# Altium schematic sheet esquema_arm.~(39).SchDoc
size A4
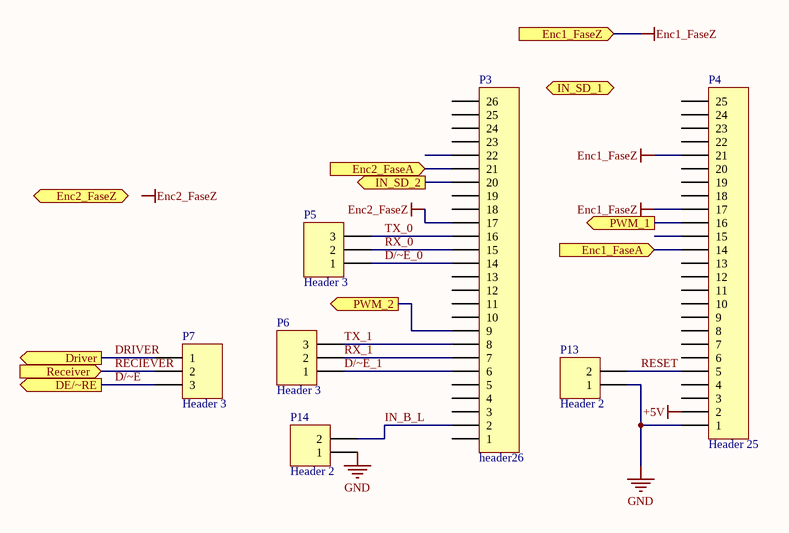
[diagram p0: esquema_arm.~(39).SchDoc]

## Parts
P3  header26  [HDR1x26]
P4  Header 25  [HDR1X25]
P5  Header 3  [HDR1X3]
P6  Header 3  [HDR1X3]
P7  Header 3  [HDR1X3]
P13  Header 2  [wf2s]
P14  Header 2  [wf2s]

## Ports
DE/~RE (out), Driver (out), Enc1_FaseA (in), Enc1_FaseZ (in), Enc2_FaseA (in), Enc2_FaseZ (in), IN_SD_1 (out), IN_SD_2 (out), PWM_1 (out), PWM_2 (out), Receiver (in)

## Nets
+5V: P4.2
Enc1_FaseZ: P4.17 P4.21 ; port Enc1_FaseZ
Enc2_FaseZ: P3.17
GND: P4.1 P13.1 P14.1
D/~E: P7.3 ; port DE/~RE
D/~E_0: P3.14 P5.1
D/~E_1: P3.6 P6.1
DRIVER: P7.1 ; port Driver
Enc1_FaseA: P4.14 ; port Enc1_FaseA
Enc2_FaseA: P3.21 ; port Enc2_FaseA
IN_B_L: P3.2 P14.2
IN_SD_2: P3.20 ; port IN_SD_2
PWM_1: P4.16 ; port PWM_1
PWM_2: P3.9 ; port PWM_2
RECIEVER: P7.2 ; port Receiver
RESET: P4.5 P13.2
RX_0: P3.15 P5.2
RX_1: P3.7 P6.2
TX_0: P3.16 P5.3
TX_1: P3.8 P6.3

Not connected (* = marked no-connect by the designer): P3 1 3 4 5 10 11 12 13 18 19 22 23 24 25 26; P4 3 4 6 7 8 9 10 11 12 13 15 18 19 20 22 23 24 25

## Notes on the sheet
- Labels drawn without touching a wire or pin: Enc2_FaseZ

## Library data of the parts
P3 = Component_1
P4 = Header 25: Header, 25-Pin
P5-P7 = Header 3: Header, 3-Pin
P13 P14 = Header 2: Header, 2-Pin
